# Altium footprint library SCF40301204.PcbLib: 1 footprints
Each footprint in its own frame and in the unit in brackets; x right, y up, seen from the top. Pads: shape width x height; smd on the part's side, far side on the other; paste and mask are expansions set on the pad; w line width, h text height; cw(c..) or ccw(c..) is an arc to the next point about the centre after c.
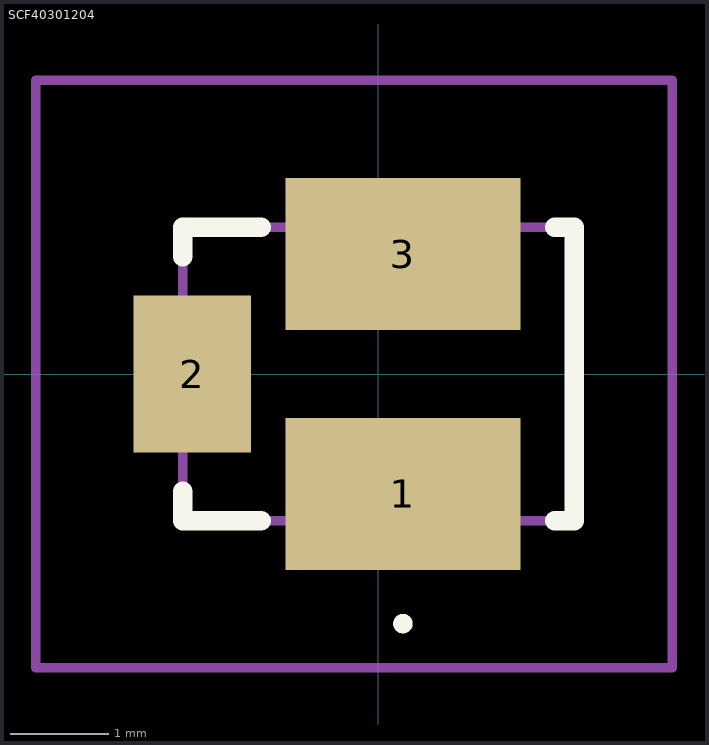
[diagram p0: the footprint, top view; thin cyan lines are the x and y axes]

## SCF40301204 [mm]
pads (3):
  rect 2.4x1.55 smd: 1(0.25,-1.225) 3(0.25,1.225)
  rect 1.2x1.6 smd: 2(-1.9,0)
Top Overlay:
  lines w0.1: 0.25,-2.6 cw(c0.25,-2.55) 0.25,-2.5 ; 0.25,-2.6 0.25,-2.6 ; 0.25,-2.6 ccw(c0.25,-2.55) 0.25,-2.5 ; 0.25,-2.5 0.25,-2.5
  lines w0.2: -2,-1.2 -2,-1.5 -1.2,-1.5 ; -2,1.2 -2,1.5 -1.2,1.5 ; 1.8,-1.5 2,-1.5 2,1.5 1.8,1.5
Mechanical 15:
  lines w0.1: -2,-1.5 2,-1.5 2,1.5 -2,1.5 -2,-1.5
Mechanical 20:
  lines w0.1: -3.5,-3 3,-3 3,3 -3.5,3 -3.5,-3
